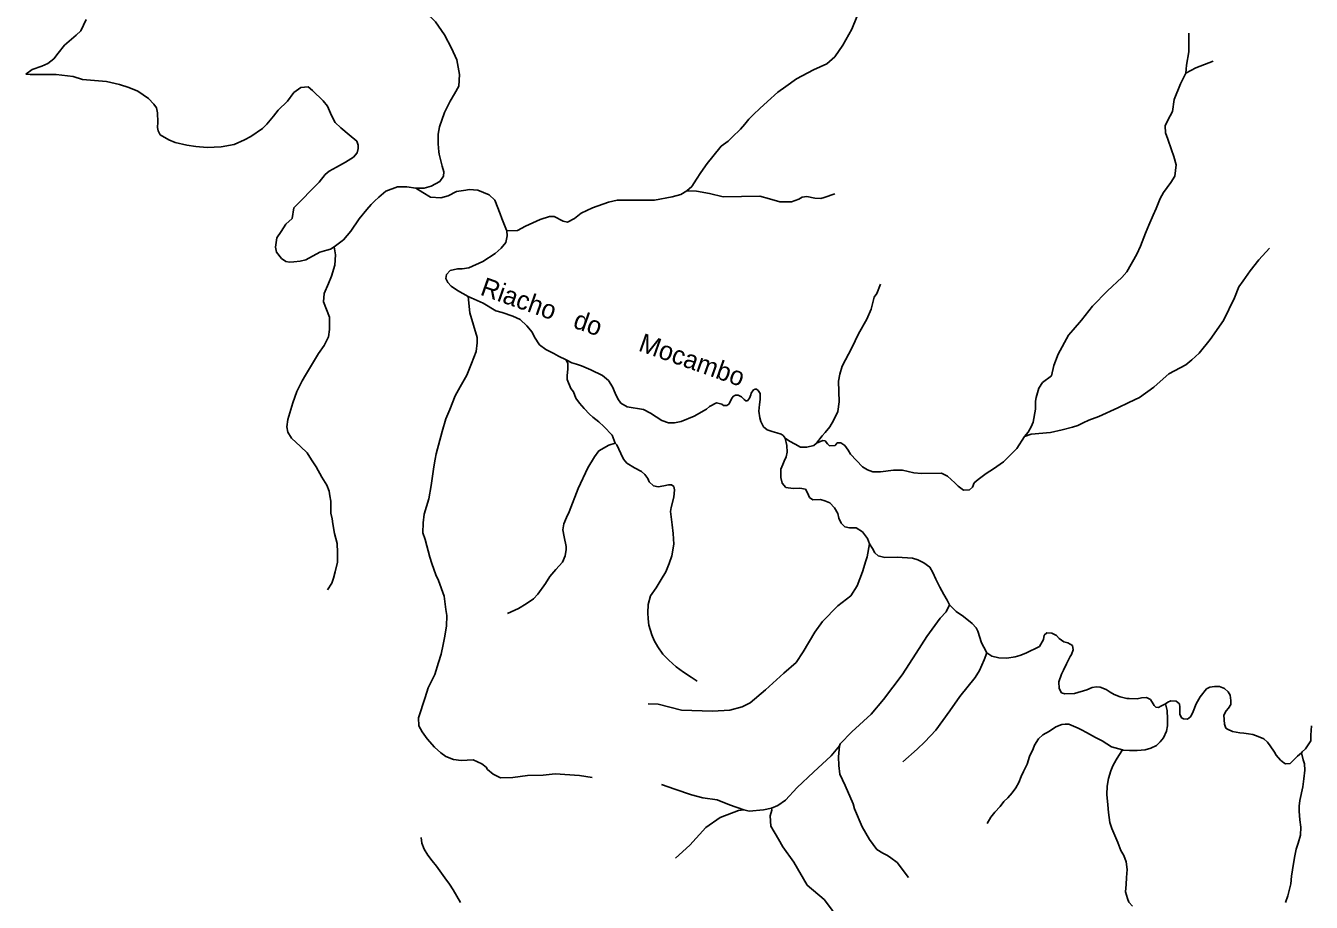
# Model space of a CAD drawing. Extents: x 717.8 to 772.7, y 8672.2 to 8728.
# Drawn here: x 717.99 to 731.77, y 8693.87 to 8703.27 of the extents above; entities that cross this region are included whole.
import ezdxf
from ezdxf.enums import TextEntityAlignment as Align

# ---------------------------------------------------------------- set-up
doc = ezdxf.new("R2010")
doc.units = 0
doc.header["$LTSCALE"] = 0.08
doc.linetypes.add('LONG_DASHED', pattern=[7.5, 6, -1.5])
doc.layers.add('61', color=7, linetype='Continuous')
doc.layers.add('9', color=7, linetype='LONG_DASHED', lineweight=25)

msp = doc.modelspace()

# ---------------------------------------------------------------- linework, layer by layer
at = {"layer": '9'}
for points in [[(722.173, 8701.53), (722.2166, 8701.5283), (722.2617, 8701.5302), (722.3386, 8701.5499), (722.4316, 8701.5997), (722.4716, 8701.6565), (722.4748, 8701.7047), (722.4547, 8701.7655), (722.4245, 8701.8921), (722.4195, 8701.9175), (722.4145, 8702.0036), (722.4121, 8702.1059), (722.4263, 8702.1879), (722.483, 8702.3417), (722.5419, 8702.4599), (722.5876, 8702.5409), (722.6333, 8702.6221), (722.6436, 8702.7487), (722.6124, 8702.9047), (722.5578, 8703.0302), (722.4819, 8703.1719), (722.3837, 8703.3136), (722.3311, 8703.3663), (722.28, 8703.4458)], [(718.639, 8703.3372), (718.5839, 8703.2159), (718.5329, 8703.1702), (718.4071, 8703.0634), (718.3392, 8702.975), (718.2951, 8702.9154), (718.2295, 8702.8665), (718.1638, 8702.8362), (718.06, 8702.7995), (717.9921, 8702.7517), (718.0404, 8702.7481), (718.1134, 8702.749), (718.3203, 8702.7489), (718.5006, 8702.7251), (718.5996, 8702.6936), (718.8598, 8702.6738), (718.9966, 8702.642), (719.0976, 8702.6064), (719.1938, 8702.5688), (719.3078, 8702.4909), (719.3659, 8702.4301), (719.3951, 8702.3885), (719.4055, 8702.3351), (719.41, 8702.2363), (719.4048, 8702.1806), (719.413, 8702.1441), (719.4348, 8702.0997), (719.525, 8702.0457), (719.594, 8702.017), (719.7203, 8701.9883), (719.8159, 8701.9754), (719.9373, 8701.9632), (720.0889, 8701.9734), (720.2255, 8701.9967), (720.3382, 8702.0468), (720.4039, 8702.0823), (720.5305, 8702.1685), (720.576, 8702.2142), (720.647, 8702.3003), (720.6971, 8702.3659), (720.799, 8702.4626), (720.865, 8702.5538), (720.9409, 8702.6097), (721.0196, 8702.6156), (721.066, 8702.5752), (721.1808, 8702.4643), (721.2287, 8702.4088), (721.269, 8702.3075), (721.3099, 8702.2327), (721.3712, 8702.176), (721.4607, 8702.1009), (721.5418, 8702.0341), (721.5569, 8701.9885), (721.5568, 8701.953), (721.5467, 8701.9089), (721.506, 8701.8618), (721.4199, 8701.806), (721.3237, 8701.7552), (721.2433, 8701.7124), (721.203, 8701.6748), (721.1395, 8701.5928), (720.8669, 8701.3177), (720.8471, 8701.2049), (720.7811, 8701.1424), (720.7288, 8701.0641), (720.6838, 8700.9944), (720.6694, 8700.894), (720.6803, 8700.8407), (720.7336, 8700.7738), (720.7794, 8700.7437), (720.8197, 8700.7355), (720.8646, 8700.7384), (720.9343, 8700.7439), (720.9951, 8700.7616), (721.144, 8700.8423), (721.2205, 8700.8621), (721.2607, 8700.8757), (721.2969, 8700.8998)], [(726.9025, 8703.3669), (726.8477, 8703.2347), (726.7524, 8703.0621), (726.6639, 8702.9357), (726.5801, 8702.8637), (726.435, 8702.7977), (726.2536, 8702.6997), (726.1394, 8702.6199), (726.0558, 8702.5595), (725.9449, 8702.4579), (725.8624, 8702.3815), (725.7951, 8702.3185), (725.7445, 8702.2679), (725.7019, 8702.2135), (725.6527, 8702.161), (725.5657, 8702.0742), (725.5213, 8702.0332), (725.4484, 8701.9801), (725.3581, 8701.8668), (725.2953, 8701.7943), (725.2277, 8701.6978), (725.1841, 8701.6254), (725.134, 8701.5447), (725.0795, 8701.4988)], [(730.46, 8703.1922), (730.4606, 8702.9899), (730.4345, 8702.8491), (730.4269, 8702.7618)], [(730.7199, 8702.8901), (730.5334, 8702.8173), (730.4269, 8702.7618)], [(730.4269, 8702.7618), (730.4018, 8702.7119), (730.3719, 8702.649), (730.3023, 8702.4806), (730.2853, 8702.3503), (730.2337, 8702.259), (730.2053, 8702.1981), (730.2092, 8702.1214), (730.2353, 8702.0534), (730.2748, 8701.9403), (730.2986, 8701.8683), (730.323, 8701.7789), (730.3112, 8701.6571), (730.2677, 8701.5891), (730.1871, 8701.4823), (730.1523, 8701.4159), (730.1089, 8701.3099), (730.078, 8701.2372), (730.0305, 8701.1304), (729.9973, 8701.0473), (729.9404, 8700.9074), (729.9021, 8700.8202), (729.7942, 8700.6313), (729.7428, 8700.5688), (729.5886, 8700.4289), (729.4273, 8700.2628), (729.3095, 8700.1121), (729.2217, 8700.0089), (729.1719, 8699.9512), (729.0604, 8699.7487), (729.0114, 8699.6269), (728.9869, 8699.5154), (728.8897, 8699.4434), (728.851, 8699.3825), (728.8234, 8699.2823), (728.8156, 8699.2434), (728.8157, 8699.1581), (728.7924, 8699.0182), (728.7691, 8698.9701), (728.7371, 8698.9103), (728.6968, 8698.866)], [(721.2969, 8700.8998), (721.3983, 8700.9759), (721.4762, 8701.0683), (721.5663, 8701.2012), (721.6501, 8701.2981), (721.6937, 8701.3521), (721.7321, 8701.3882), (721.7771, 8701.4329), (721.8521, 8701.4967), (721.9784, 8701.5435), (722.078, 8701.5413), (722.173, 8701.53)], [(723.1504, 8701.0709), (723.1386, 8701.0961), (723.0952, 8701.2019), (723.0766, 8701.2518), (723.0208, 8701.4011), (722.9586, 8701.4572), (722.8385, 8701.5079), (722.7458, 8701.514), (722.7102, 8701.5079), (722.6103, 8701.4942), (722.5199, 8701.4478), (722.4405, 8701.4244), (722.3305, 8701.4315), (722.2507, 8701.4832), (722.173, 8701.53)], [(725.0795, 8701.4988), (725.015, 8701.461), (724.9219, 8701.4338), (724.7326, 8701.3993), (724.3334, 8701.4002), (724.2398, 8701.3792), (724.066, 8701.3173), (723.9471, 8701.2604), (723.8758, 8701.2021), (723.8002, 8701.1645), (723.7523, 8701.1749), (723.6583, 8701.2252), (723.6072, 8701.2251), (723.5067, 8701.194), (723.3493, 8701.1194), (723.2646, 8701.0742), (723.1504, 8701.0709)], [(726.6642, 8701.4663), (726.5517, 8701.427), (726.5158, 8701.4184), (726.4512, 8701.421), (726.3636, 8701.4375), (726.315, 8701.4302), (726.278, 8701.4111), (726.2012, 8701.3822), (726.0768, 8701.3822), (725.9643, 8701.4148), (725.8632, 8701.4428), (725.4674, 8701.4355), (725.321, 8701.4701), (725.1839, 8701.4954), (725.0795, 8701.4988)], [(722.736, 8700.3667), (722.6219, 8700.432), (722.5515, 8700.4775), (722.5153, 8700.515), (722.497, 8700.5604), (722.5025, 8700.602), (722.5423, 8700.647), (722.6209, 8700.6644), (722.6699, 8700.664), (722.7415, 8700.6739), (722.8939, 8700.7432), (723.0241, 8700.8275), (723.0886, 8700.8844), (723.1401, 8700.9469), (723.1535, 8701.0173), (723.1504, 8701.0709)], [(721.2259, 8697.219), (721.272, 8697.2918), (721.2924, 8697.3466), (721.3107, 8697.4143), (721.333, 8697.5177), (721.3358, 8697.6228), (721.3303, 8697.7178), (721.3025, 8697.826), (721.2827, 8697.9285), (721.2772, 8697.9825), (721.2636, 8698.0445), (721.2636, 8698.1729), (721.2533, 8698.2303), (721.2438, 8698.2783), (721.2185, 8698.3426), (721.1646, 8698.4286), (721.1058, 8698.5386), (721.0568, 8698.6161), (721.0083, 8698.6892), (720.9373, 8698.7589), (720.8424, 8698.847), (720.8016, 8698.9117), (720.7927, 8698.9671), (720.8009, 8699.047), (720.8569, 8699.2273), (720.8994, 8699.346), (720.954, 8699.4608), (720.9897, 8699.522), (721.1302, 8699.7566), (721.1905, 8699.8417), (721.2369, 8699.9353), (721.2499, 8700.0139), (721.2475, 8700.1436), (721.1846, 8700.3104), (721.1901, 8700.3978), (721.2372, 8700.5064), (721.2715, 8700.5848), (721.3067, 8700.7022), (721.3113, 8700.8151), (721.2969, 8700.8998)], [(731.3249, 8700.8864), (731.2109, 8700.7591), (731.1187, 8700.6414), (731.0441, 8700.5346), (730.995, 8700.4711), (730.9496, 8700.3537), (730.8334, 8700.1109), (730.6884, 8699.9052), (730.5722, 8699.7572), (730.4916, 8699.6866), (730.4263, 8699.6342), (730.2467, 8699.5386), (730.1535, 8699.4552), (730.0863, 8699.3959), (729.9296, 8699.2852), (729.8186, 8699.2292), (729.6993, 8699.1739), (729.4939, 8699.0807), (729.3893, 8699.0416), (729.3276, 8699.0133), (729.2717, 8698.9832), (729.2133, 8698.964), (729.101, 8698.9358), (728.9769, 8698.9093), (728.7704, 8698.8897), (728.6968, 8698.866)], [(727.1561, 8700.5002), (727.1165, 8700.3982), (727.0881, 8700.3587), (727.0565, 8700.2313), (727.008, 8700.123), (726.9187, 8699.965), (726.846, 8699.8168), (726.7456, 8699.619), (726.7197, 8699.5326), (726.7062, 8699.4576), (726.7117, 8699.2361), (726.6967, 8699.1325), (726.6514, 8699.0385), (726.6102, 8698.9698), (726.5631, 8698.907), (726.5279, 8698.8739), (726.4677, 8698.7949)], [(722.736, 8700.3667), (722.7514, 8700.1913), (722.7925, 8700.0584), (722.8311, 8699.9273), (722.8311, 8699.8687), (722.8217, 8699.7766), (722.7711, 8699.6475), (722.7211, 8699.524), (722.6483, 8699.3961), (722.5939, 8699.3018), (722.5384, 8699.1535), (722.4939, 8699.0529), (722.4565, 8698.9191), (722.3933, 8698.6807), (722.3812, 8698.6218), (722.368, 8698.5383), (722.34, 8698.3414), (722.3141, 8698.1977), (722.2621, 8698.0331), (722.2528, 8697.9389), (722.2497, 8697.8306), (722.2748, 8697.759), (722.3253, 8697.5727), (722.3463, 8697.5026), (722.3881, 8697.3822), (722.4178, 8697.3195), (722.4779, 8697.1511), (722.4957, 8697.0106), (722.5065, 8696.9447)], [(723.784, 8699.6881), (723.7032, 8699.7254), (723.6534, 8699.7565), (723.5689, 8699.7984), (723.5002, 8699.8482), (723.4477, 8699.9303), (723.4193, 8699.9825), (723.3644, 8700.0506), (723.2913, 8700.121), (723.2154, 8700.156), (723.1007, 8700.1953), (723.0303, 8700.2142), (722.8941, 8700.2961), (722.736, 8700.3667)], [(724.312, 8698.7927), (724.2779, 8698.8789), (724.1886, 8698.9718), (724.1355, 8699.0228), (724.0716, 8699.0725), (724.0358, 8699.106), (723.9776, 8699.1641), (723.9281, 8699.2211), (723.8882, 8699.2765), (723.8631, 8699.3434), (723.8352, 8699.3788), (723.7958, 8699.4752), (723.7978, 8699.521), (723.8033, 8699.5883), (723.8022, 8699.6487), (723.784, 8699.6881)], [(726.1323, 8698.8457), (726.1115, 8698.8756), (726.091, 8698.8917), (726.0439, 8698.9044), (725.9929, 8698.9194), (725.9385, 8698.9366), (725.9021, 8698.9704), (725.8721, 8699.0269), (725.8622, 8699.0641), (725.8521, 8699.1379), (725.8594, 8699.2094), (725.8666, 8699.2615), (725.8637, 8699.3256), (725.8433, 8699.3602), (725.825, 8699.3735), (725.8106, 8699.3735), (725.7918, 8699.3652), (725.7702, 8699.3314), (725.7652, 8699.3125), (725.7513, 8699.2745), (725.728, 8699.2465), (725.7109, 8699.246), (725.6926, 8699.2615), (725.6638, 8699.2909), (725.6305, 8699.309), (725.6006, 8699.3086), (725.5779, 8699.2964), (725.5618, 8699.2747), (725.5446, 8699.2381), (725.528, 8699.2109), (725.507, 8699.1965), (725.472, 8699.1971), (725.4532, 8699.2137), (725.3972, 8699.2249), (725.3235, 8699.1872), (725.2897, 8699.1568), (725.1578, 8699.0819), (725.0176, 8699.0246), (724.9467, 8699.012), (724.8808, 8699.0122), (724.8093, 8699.037), (724.689, 8699.114), (724.6148, 8699.1557), (724.4386, 8699.1833), (724.3726, 8699.2221), (724.3397, 8699.2674), (724.3115, 8699.3292), (724.2838, 8699.3996), (724.2401, 8699.4664), (724.174, 8699.5199), (724.0499, 8699.5787), (723.9514, 8699.6246), (723.8959, 8699.6393), (723.8463, 8699.657), (723.784, 8699.6881)], [(728.6968, 8698.866), (728.6177, 8698.7369), (728.4725, 8698.593), (728.3661, 8698.5182), (728.2861, 8698.4691), (728.2004, 8698.4053), (728.1591, 8698.3666), (728.1404, 8698.3208), (728.1075, 8698.2917), (728.0443, 8698.2904), (727.9882, 8698.3324), (727.9514, 8698.3679), (727.8734, 8698.4395), (727.8095, 8698.4711), (727.5934, 8698.4672), (727.5134, 8698.4755), (727.3915, 8698.5033), (727.2953, 8698.504), (727.1554, 8698.486), (727.0728, 8698.4853), (727.0167, 8698.5073), (726.9612, 8698.5408), (726.8346, 8698.6744), (726.8096, 8698.7168), (726.7734, 8698.7692), (726.7295, 8698.797), (726.6901, 8698.7961), (726.6682, 8698.7683), (726.6076, 8698.7657), (726.5876, 8698.7851), (726.5605, 8698.8186), (726.5353, 8698.8225), (726.4677, 8698.7949)], [(723.155, 8696.9655), (723.2739, 8697.0222), (723.3557, 8697.0688), (723.4342, 8697.1245), (723.4829, 8697.1732), (723.5629, 8697.2885), (723.6112, 8697.3637), (723.6738, 8697.4404), (723.7453, 8697.519), (723.775, 8697.5871), (723.7852, 8697.6547), (723.7838, 8697.6868), (723.7654, 8697.7882), (723.748, 8697.8655), (723.7617, 8697.9295), (723.7896, 8697.9953), (723.8189, 8698.0581), (723.9129, 8698.3072), (724.018, 8698.5297), (724.0887, 8698.6475), (724.1362, 8698.7113), (724.2412, 8698.7731), (724.312, 8698.7927)], [(725.1907, 8696.2425), (725.124, 8696.2836), (725.0421, 8696.3384), (724.9658, 8696.3947), (724.8849, 8696.4681), (724.8228, 8696.5309), (724.7687, 8696.611), (724.7284, 8696.678), (724.7029, 8696.737), (724.6724, 8696.8426), (724.6659, 8696.9111), (724.6609, 8696.9727), (724.6644, 8697.0633), (724.6887, 8697.1579), (724.749, 8697.2425), (724.805, 8697.3325), (724.8521, 8697.4139), (724.8896, 8697.5021), (724.9184, 8697.5856), (724.9384, 8697.7106), (724.934, 8697.8234), (724.9232, 8697.9169), (724.9096, 8698.0019), (724.9039, 8698.0601), (724.9105, 8698.1046), (724.9407, 8698.2161), (724.9479, 8698.2914), (724.9409, 8698.3281), (724.9146, 8698.3479), (724.8812, 8698.347), (724.8333, 8698.3348), (724.7733, 8698.3252), (724.7218, 8698.3372), (724.6736, 8698.3782), (724.6609, 8698.4137), (724.6274, 8698.4575), (724.5928, 8698.4909), (724.5162, 8698.5288), (724.4375, 8698.578), (724.3993, 8698.6227), (724.3709, 8698.683), (724.3284, 8698.7752), (724.312, 8698.7927)], [(727.0378, 8697.7131), (727.0163, 8697.7707), (726.9602, 8697.8432), (726.8955, 8697.8843), (726.8224, 8697.8851), (726.7735, 8697.8959), (726.7319, 8697.9365), (726.7098, 8697.99), (726.6969, 8698.0393), (726.662, 8698.101), (726.6106, 8698.1543), (726.5593, 8698.1769), (726.5134, 8698.1883), (726.4301, 8698.1873), (726.3929, 8698.2104), (726.3709, 8698.2619), (726.3504, 8698.2999), (726.2913, 8698.3123), (726.2177, 8698.3071), (726.1401, 8698.3169), (726.1, 8698.3647), (726.0862, 8698.4267), (726.0867, 8698.5131), (726.1072, 8698.5646), (726.1221, 8698.5995), (726.1422, 8698.6458), (726.1545, 8698.6988), (726.1526, 8698.7692), (726.1323, 8698.8457)], [(726.4677, 8698.7949), (726.4404, 8698.7677), (726.3668, 8698.7492), (726.2974, 8698.7508), (726.2393, 8698.7827), (726.1797, 8698.8166), (726.1323, 8698.8457)], [(724.6638, 8695.9969), (724.7734, 8695.9934), (725.0208, 8695.9309), (725.3556, 8695.9194), (725.5394, 8695.9317), (725.6723, 8695.9672), (725.7574, 8696.0091), (725.9213, 8696.1472), (726.1204, 8696.3259), (726.2526, 8696.4415), (726.3242, 8696.555), (726.4521, 8696.7657), (726.5339, 8696.8827), (726.6969, 8697.0479), (726.8382, 8697.155), (726.9046, 8697.2621), (726.9623, 8697.4136), (726.9973, 8697.5306), (727.0102, 8697.5747), (727.0378, 8697.7131)], [(727.8962, 8697.0598), (727.8678, 8697.1104), (727.8349, 8697.171), (727.79, 8697.249), (727.7478, 8697.3356), (727.7142, 8697.4061), (727.6821, 8697.4628), (727.6196, 8697.5111), (727.5566, 8697.5442), (727.4994, 8697.5597), (727.3349, 8697.5693), (727.2025, 8697.5681), (727.1308, 8697.5846), (727.0955, 8697.6188), (727.0688, 8697.6653), (727.0378, 8697.7131)], [(722.5065, 8696.9447), (722.5039, 8696.8295), (722.4799, 8696.7067), (722.4672, 8696.6351), (722.4465, 8696.5314), (722.4186, 8696.4401), (722.3769, 8696.3112)], [(726.7157, 8695.5471), (726.724, 8695.5682), (726.8471, 8695.6992), (727.0553, 8695.8888), (727.1864, 8696.043), (727.3854, 8696.3074), (727.5375, 8696.5414), (727.6532, 8696.7199), (727.7081, 8696.7988), (727.7949, 8696.9157), (727.8578, 8696.9848), (727.8962, 8697.0598)], [(727.8962, 8697.0598), (727.9653, 8696.9878), (728.0443, 8696.9364), (728.1378, 8696.8581), (728.1794, 8696.8147), (728.1977, 8696.777), (728.2389, 8696.6533), (728.2626, 8696.6041), (728.293, 8696.5446)], [(728.293, 8696.5446), (728.347, 8696.5081), (728.422, 8696.4912), (728.5084, 8696.4892), (728.5995, 8696.5024), (728.649, 8696.5171), (728.7141, 8696.542), (728.8589, 8696.6131), (728.9004, 8696.6874), (728.9085, 8696.7361), (728.9394, 8696.7593), (728.9929, 8696.7561), (729.0409, 8696.7324), (729.071, 8696.6973), (729.1212, 8696.6622), (729.1629, 8696.6524), (729.2115, 8696.6221), (729.2189, 8696.5783), (729.2016, 8696.527), (729.1871, 8696.5068), (729.147, 8696.4267), (729.1172, 8696.3587), (729.0966, 8696.3156), (729.0663, 8696.235), (729.0713, 8696.1611), (729.0964, 8696.116), (729.1293, 8696.1044), (729.2356, 8696.1083), (729.365, 8696.1476), (729.423, 8696.1733), (729.4687, 8696.1811), (729.5106, 8696.1779), (729.5743, 8696.1521), (729.6162, 8696.1234), (729.66, 8696.0983), (729.7257, 8696.0719), (729.7959, 8696.0567), (729.8211, 8696.0542), (729.9061, 8696.0516), (729.9524, 8696.0638), (730.0072, 8696.0664), (730.0503, 8696.0432), (730.0777, 8695.9974), (730.0878, 8695.9793), (730.107, 8695.962), (730.1366, 8695.9595), (730.1604, 8695.973), (730.2083, 8695.9973)], [(727.3932, 8695.3759), (727.5491, 8695.5125), (727.6302, 8695.5891), (727.7498, 8695.7149), (727.8971, 8695.9219), (728.0059, 8696.0761), (728.1695, 8696.2806), (728.2166, 8696.3541), (728.2667, 8696.4715), (728.293, 8696.5446)], [(722.3769, 8696.3112), (722.3073, 8696.1694), (722.2731, 8696.0647), (722.2029, 8695.8493), (722.2067, 8695.7607), (722.2421, 8695.6967), (722.2953, 8695.6227), (722.3745, 8695.5322), (722.4403, 8695.4727), (722.4941, 8695.4334), (722.5764, 8695.4024), (722.6606, 8695.3898), (722.789, 8695.3973), (722.8821, 8695.3562), (722.9277, 8695.3201), (722.9428, 8695.2941), (723.0036, 8695.2447), (723.0808, 8695.2042), (723.215, 8695.2093), (723.3714, 8695.2302), (723.5391, 8695.2346), (723.6681, 8695.2464), (723.9284, 8695.2289), (724.0638, 8695.2068)], [(731.6668, 8695.4738), (731.6252, 8695.4355), (731.5738, 8695.388), (731.5463, 8695.3573), (731.4952, 8695.3547), (731.4774, 8695.3656), (731.4413, 8695.3927), (731.3956, 8695.4468), (731.3769, 8695.4803), (731.3336, 8695.5487), (731.3041, 8695.5879), (731.2638, 8695.622), (731.205, 8695.6476), (731.1444, 8695.6702), (731.0993, 8695.6753), (731.0491, 8695.685), (731.0059, 8695.6882), (730.9273, 8695.7011), (730.8739, 8695.7256), (730.8583, 8695.7373), (730.8413, 8695.7785), (730.8359, 8695.8783), (730.8617, 8695.9225), (730.8862, 8695.9517), (730.9119, 8695.9904), (730.9115, 8696.034), (730.9023, 8696.0921), (730.881, 8696.125), (730.843, 8696.1643), (730.7896, 8696.1823), (730.7342, 8696.183), (730.6839, 8696.1759), (730.6485, 8696.1585), (730.5828, 8696.0721), (730.5397, 8695.9972), (730.5081, 8695.9162), (730.481, 8695.8615), (730.4443, 8695.8351), (730.4012, 8695.8363), (730.3831, 8695.8492), (730.364, 8695.889), (730.364, 8695.9641), (730.3613, 8695.9967), (730.3227, 8696.0264), (730.266, 8696.0289), (730.2351, 8696.0173), (730.2083, 8695.9973)], [(729.749, 8695.5042), (729.756, 8695.5017), (729.8258, 8695.4965), (729.906, 8695.4964), (729.9914, 8695.5042), (730.0534, 8695.5222), (730.1133, 8695.5528), (730.1522, 8695.5918), (730.1894, 8695.6325), (730.2213, 8695.7052), (730.2328, 8695.761), (730.2322, 8695.8357), (730.2261, 8695.9272), (730.2083, 8695.9973)], [(728.2974, 8694.7143), (728.3381, 8694.7843), (728.3789, 8694.8357), (728.4393, 8694.8975), (728.478, 8694.9492), (728.5188, 8694.9898), (728.5658, 8695.0448), (728.6046, 8695.0964), (728.6381, 8695.1533), (728.6639, 8695.2179), (728.6879, 8695.2734), (728.726, 8695.3505), (728.7535, 8695.4329), (728.7898, 8695.5162), (728.8045, 8695.5565), (728.8492, 8695.6235), (728.8949, 8695.6651), (728.968, 8695.7049), (729.0326, 8695.7519), (729.099, 8695.7759), (729.1336, 8695.7794), (729.1743, 8695.7785), (729.2735, 8695.7387), (729.3081, 8695.7182), (729.3648, 8695.6899), (729.4613, 8695.6359), (729.5295, 8695.5995), (729.6296, 8695.5366), (729.749, 8695.5042)], [(731.7741, 8695.7607), (731.7696, 8695.6629), (731.7666, 8695.6019), (731.7386, 8695.5589), (731.7116, 8695.5139), (731.675, 8695.4827), (731.6668, 8695.4738)], [(725.9868, 8694.8792), (726.0547, 8694.9072), (726.1348, 8694.9649), (726.2623, 8695.1), (726.4374, 8695.2662), (726.6247, 8695.4417), (726.7157, 8695.5471)], [(727.4539, 8694.1349), (727.3334, 8694.2953), (727.267, 8694.3476), (727.2289, 8694.3715), (727.1802, 8694.3963), (727.1164, 8694.4371), (727.0376, 8694.5425), (726.9587, 8694.6781), (726.8764, 8694.8715), (726.8613, 8694.9246), (726.7765, 8695.1238), (726.7206, 8695.2437), (726.7082, 8695.3367), (726.7061, 8695.4283), (726.7157, 8695.5471)], [(729.8569, 8693.829), (729.8154, 8693.8704), (729.8025, 8693.9092), (729.7818, 8693.9817), (729.787, 8694.0619), (729.7922, 8694.1343), (729.7998, 8694.2197), (729.7882, 8694.305), (729.765, 8694.3697), (729.7312, 8694.4266), (729.6976, 8694.5094), (729.6665, 8694.587), (729.6329, 8694.6595), (729.6148, 8694.7268), (729.5978, 8694.8329), (729.5901, 8694.9155), (729.5796, 8695.0242), (729.5848, 8695.1147), (729.5976, 8695.1974), (729.6235, 8695.2802), (729.6466, 8695.3319), (729.6828, 8695.3965), (729.7113, 8695.443), (729.749, 8695.5042)], [(731.6668, 8695.4738), (731.6873, 8695.3991), (731.7015, 8695.3528), (731.7048, 8695.2851), (731.6925, 8695.1949), (731.6816, 8695.1089), (731.6496, 8694.9619), (731.6436, 8694.8988), (731.6428, 8694.8466), (731.6505, 8694.7535), (731.6591, 8694.6757), (731.6559, 8694.5893), (731.6314, 8694.5036), (731.6114, 8694.4392), (731.5966, 8694.3677), (731.5834, 8694.2853), (731.5615, 8694.1481), (731.5537, 8694.0679), (731.5206, 8693.9379), (731.4966, 8693.8659)], [(724.8066, 8695.1325), (724.9494, 8695.084), (725.1305, 8695.022), (725.2501, 8694.991), (725.4049, 8694.967), (725.5351, 8694.9132), (725.6916, 8694.8609)], [(725.6916, 8694.8609), (725.7478, 8694.8464), (725.9005, 8694.862), (725.9868, 8694.8792)], [(727.6242, 8693.16), (727.5937, 8693.1897), (727.5249, 8693.2957), (727.3835, 8693.4426), (727.2189, 8693.5703), (727.1011, 8693.645), (727.0156, 8693.6793), (726.816, 8693.6757), (726.7062, 8693.718), (726.6415, 8693.7801), (726.5497, 8693.8998), (726.369, 8694.0529), (726.2242, 8694.2994), (726.1082, 8694.4641), (726.0605, 8694.5459), (725.9788, 8694.6864), (725.9727, 8694.7977), (725.99, 8694.8571), (725.9868, 8694.8792)], [(724.9569, 8694.3434), (725.11, 8694.4815), (725.2839, 8694.6735), (725.4371, 8694.7775), (725.6321, 8694.8546), (725.6916, 8694.8609)], [(722.2304, 8694.566), (722.2373, 8694.5035), (722.2624, 8694.4403), (722.3026, 8694.3736), (722.3486, 8694.3134), (722.3961, 8694.2562), (722.4861, 8694.1313), (722.5346, 8694.0632), (722.5746, 8694.0045), (722.6512, 8693.8688)]]:
    msp.add_lwpolyline(points, dxfattribs=at)

# ---------------------------------------------------------------- texts
at = {"layer": '61'}
msp.add_text('Riacho   do      Mocambo', height=0.2, rotation=340.513, dxfattribs=at).set_placement((724.2544, 8699.8926), align=Align.CENTER)

doc.saveas('drawing.dxf')
